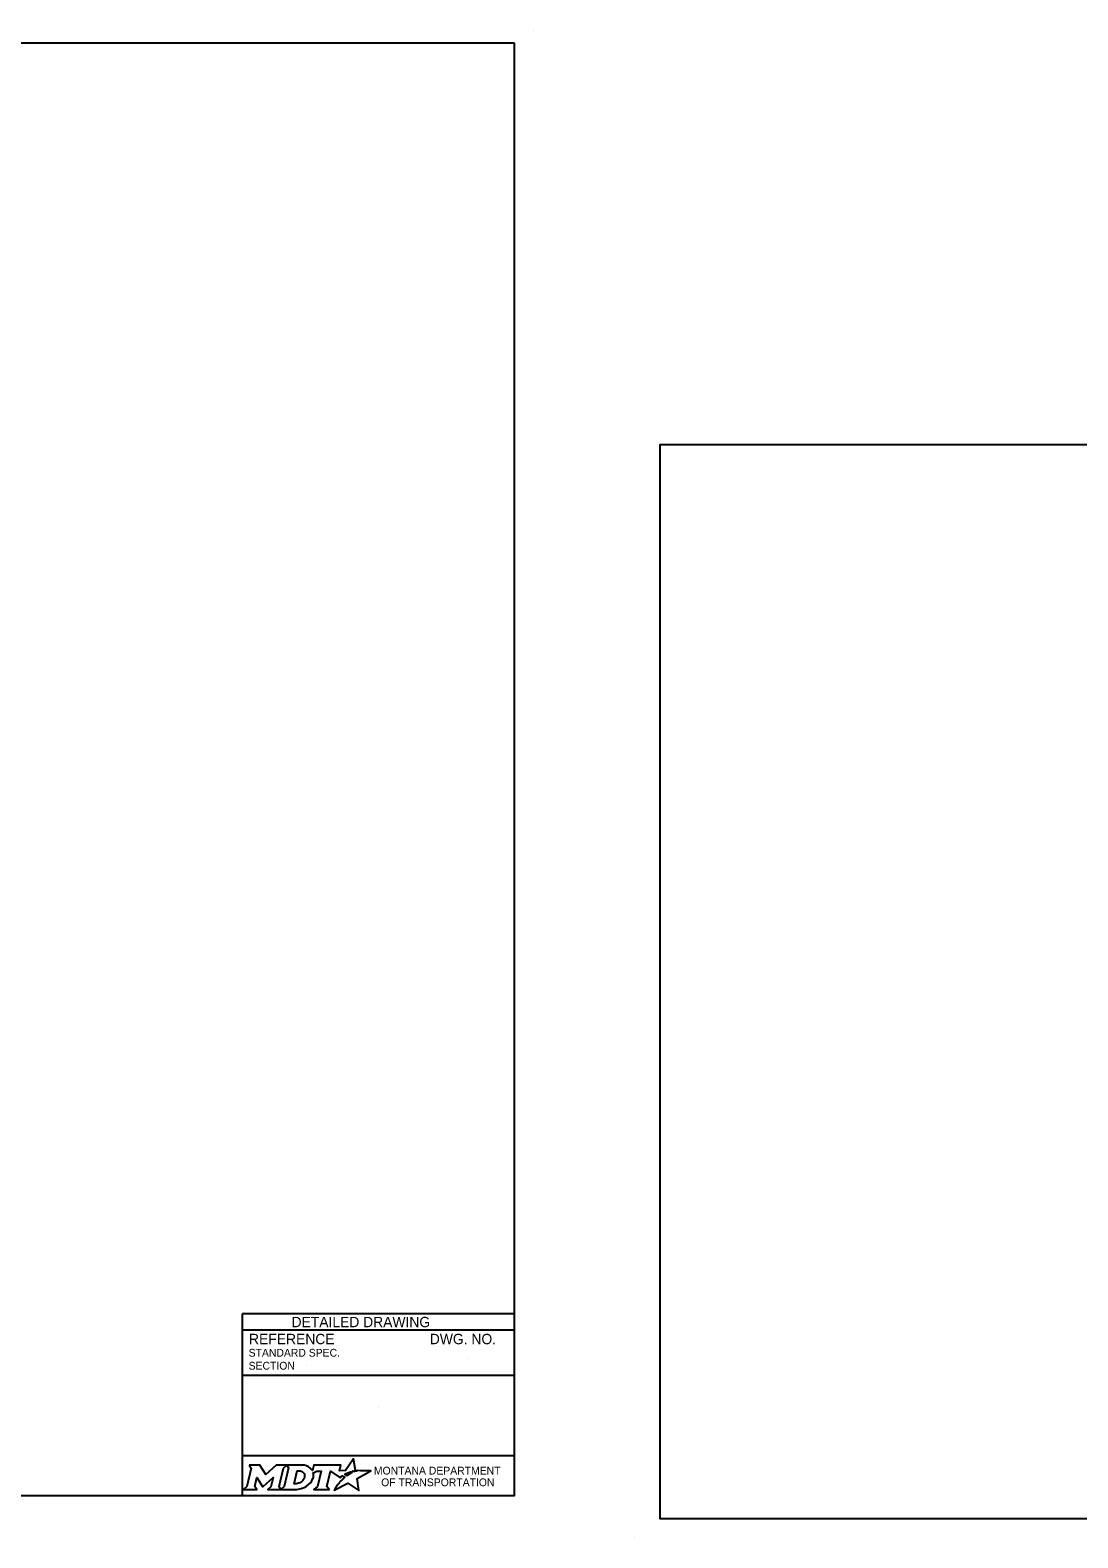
# Model space of a CAD drawing. Extents: x 49991.4 to 50021, y 49987.6 to 50011.4.
# Drawn here: x 50004.88 to 50012.96, y 49999.74 to 50011.36 of the extents above; entities that cross this region are included whole.
import ezdxf

# ---------------------------------------------------------------- set-up
doc = ezdxf.new("R2010")
doc.units = 0
doc.layers.add('Level 1', color=7, linetype='Continuous')
doc.layers.add('Level 2', color=7, linetype='Continuous')

msp = doc.modelspace()

# ---------------------------------------------------------------- linework, layer by layer
at = {"layer": 'Level 1'}
for p, q in [((50008.765, 50011.363), (50008.765, 50011.363)), ((50009.537, 49999.736), (50009.537, 49999.736))]:
    msp.add_line(p, q, dxfattribs=at)
for points in [[(50008.615, 50011.263), (50000.336, 50011.263), (50000.336, 50000.062), (50008.615, 50000.062)], [(50020.938, 50008.165), (50009.737, 50008.165), (50009.737, 49999.886), (50020.938, 49999.886)]]:
    msp.add_lwpolyline(points, close=True, dxfattribs=at)
at = {"layer": 'Level 2'}
for p, q in [((50008.615, 50001.462), (50006.515, 50001.462)), ((50006.515, 50001.462), (50006.515, 50000.062)), ((50008.615, 50001.337), (50006.515, 50001.337)), ((50007.009, 50001.063), (50007.009, 50001.063)), ((50008.251, 50001.122), (50008.251, 50001.122)), ((50008.615, 50000.987), (50006.515, 50000.987)), ((50007.565, 50000.738), (50007.565, 50000.738)), ((50008.615, 50000.369), (50006.515, 50000.369))]:
    msp.add_line(p, q, dxfattribs=at)
for points in [[(50007.377, 50000.245), (50007.367, 50000.25), (50007.378, 50000.253), (50007.39, 50000.255), (50007.373, 50000.345), (50007.313, 50000.254), (50007.266, 50000.253), (50007.276, 50000.297), (50007.067, 50000.297), (50007.057, 50000.255), (50007.051, 50000.263)], [(50006.57, 50000.297), (50006.584, 50000.274), (50006.551, 50000.131), (50006.525, 50000.108), (50006.627, 50000.108), (50006.613, 50000.131), (50006.629, 50000.201), (50006.673, 50000.132), (50006.678, 50000.132), (50006.753, 50000.202), (50006.737, 50000.13), (50006.712, 50000.108), (50006.814, 50000.108), (50006.8, 50000.132), (50006.833, 50000.274)], [(50006.833, 50000.274), (50006.859, 50000.297), (50006.776, 50000.297), (50006.697, 50000.224), (50006.652, 50000.297), (50006.57, 50000.297)], [(50006.972, 50000.297), (50006.859, 50000.297), (50006.873, 50000.275), (50006.839, 50000.131), (50006.814, 50000.108), (50006.925, 50000.108)], [(50006.996, 50000.211), (50006.995, 50000.203), (50006.992, 50000.193), (50006.988, 50000.185), (50006.982, 50000.178), (50006.976, 50000.171), (50006.968, 50000.164), (50006.959, 50000.16), (50006.95, 50000.156), (50006.941, 50000.154), (50006.932, 50000.153), (50006.916, 50000.153), (50006.94, 50000.253), (50006.956, 50000.253), (50006.963, 50000.252), (50006.971, 50000.25), (50006.977, 50000.247), (50006.983, 50000.243), (50006.988, 50000.238), (50006.992, 50000.232), (50006.995, 50000.226), (50006.996, 50000.218), (50006.996, 50000.215), (50006.996, 50000.211)], [(50007.064, 50000.238), (50007.088, 50000.251), (50007.125, 50000.251), (50007.097, 50000.131), (50007.069, 50000.108), (50007.185, 50000.108), (50007.168, 50000.131), (50007.196, 50000.251), (50007.268, 50000.2), (50007.289, 50000.215), (50007.309, 50000.204)], [(50007.253, 50000.148), (50007.237, 50000.124), (50007.233, 50000.116), (50007.227, 50000.107), (50007.225, 50000.103), (50007.33, 50000.156), (50007.414, 50000.101), (50007.401, 50000.194), (50007.508, 50000.252), (50007.458, 50000.253), (50007.428, 50000.253), (50007.407, 50000.254), (50007.401, 50000.252), (50007.396, 50000.251), (50007.387, 50000.249), (50007.377, 50000.245)], [(50007.327, 50000.217), (50007.324, 50000.215), (50007.306, 50000.225), (50007.316, 50000.231), (50007.32, 50000.233), (50007.329, 50000.237), (50007.335, 50000.239), (50007.343, 50000.243), (50007.35, 50000.245), (50007.362, 50000.238), (50007.358, 50000.236), (50007.353, 50000.233), (50007.349, 50000.231), (50007.344, 50000.228), (50007.342, 50000.227), (50007.339, 50000.225), (50007.337, 50000.224), (50007.334, 50000.222), (50007.332, 50000.221), (50007.329, 50000.219), (50007.327, 50000.217)], [(50006.97, 50000.116), (50006.979, 50000.118), (50006.992, 50000.124), (50007.012, 50000.135)], [(50007.267, 50000.164), (50007.267, 50000.164)]]:
    msp.add_lwpolyline(points, dxfattribs=at)
for centre, radius, start, end in [((50006.995, 50000.219), 0.0709, 339.5329, 15.8582), ((50006.951, 50000.236), 0.118, 300.9103, 339.1383)]:
    msp.add_arc(centre, radius, start, end, dxfattribs=at)
for centre, major_axis, ratio, start_param, end_param in [((50006.97, 50000.25), (0.0834, -0.0037), 0.568097, 0.61298, 1.570796), ((50007.026, 50000.257), (0.0361, -0.0295), 0.469099, 1.225588, 1.570796), ((50006.925, 50000.257), (0, 0.148), 0.987302, 3.139398, 3.456847), ((50007.26, 50000.156), (-0.00694, -0.00806), 0.008222, 0, 3.137361), ((50007.276, 50000.174), (-0.0098, -0.0102), 0.016458, 3.141593, 6.279097), ((50007.297, 50000.194), (-0.0112, -0.0097), 0.021651, 3.157348, 6.283185)]:
    msp.add_ellipse(centre, major_axis=major_axis, ratio=ratio, start_param=start_param, end_param=end_param, dxfattribs=at)

# ---------------------------------------------------------------- texts
for s, height, p in [('DETAILED DRAWING', 0.0799, (50006.896, 50001.36)), ('REFERENCE', 0.08, (50006.568, 50001.229)), ('DWG. NO.', 0.08, (50007.962, 50001.229)), ('STANDARD SPEC.', 0.06, (50006.565, 50001.133)), ('SECTION', 0.06, (50006.565, 50001.033)), ('MONTANA DEPARTMENT', 0.06, (50007.531, 50000.224)), ('OF TRANSPORTATION', 0.06, (50007.587, 50000.134))]:
    msp.add_text(s, height=height, dxfattribs=at).set_placement(p)

doc.saveas('drawing.dxf')
